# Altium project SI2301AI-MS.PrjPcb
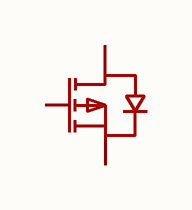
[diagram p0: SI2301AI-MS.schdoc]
1 sheet, 1 parts. Net scope: global (net labels, ports and power ports of the same name join across sheets).

## Sheet SI2301AI-MS.schdoc
size 127 x 101 mm

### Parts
Q?  si2301ai-ms  [SOT-23-3_L2.9-W1.6-P1.90-LS2.8-BR]  (value not drawn)

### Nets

Not connected (* = marked no-connect by the designer): Q? 1(G) 2(S) 3(D)

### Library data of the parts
Q? = si2301ai-ms: 数量:1个P沟道;漏源电压(Vdss):20V;连续漏极电流(Id):3A;导通电阻(RDS(on)):110mΩ@4.5V;耗散功率(Pd):1W;阈值电压(Vgs(th)):1V;; Manufacturer: MSKSEMI(美森科); AddInBom: yes; ModelId: 89cb27a44ab2466697082bb9fd73a7d0; ModelName: SOT-23-3L_L2.9-W1.6-H1.1-LS2.8-P0.95; ModelTransform: 114.173,110.236,0,90,0,0,0,0,0; Number: 1个P沟道; Drain to Source Voltage: 20V; Current - Continuous Drain(Id): 3A; Pd - Power Dissipation: 1W; Gate Threshold Voltage (Vgs(th)): 1V; Gate Charge(Qg): 12nC@4.5V; Input Capacitance(Ciss): 405pF; Reverse Transfer Capacitance (Crss@Vds): 55pF; Output Capacitance(Coss): 75pF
